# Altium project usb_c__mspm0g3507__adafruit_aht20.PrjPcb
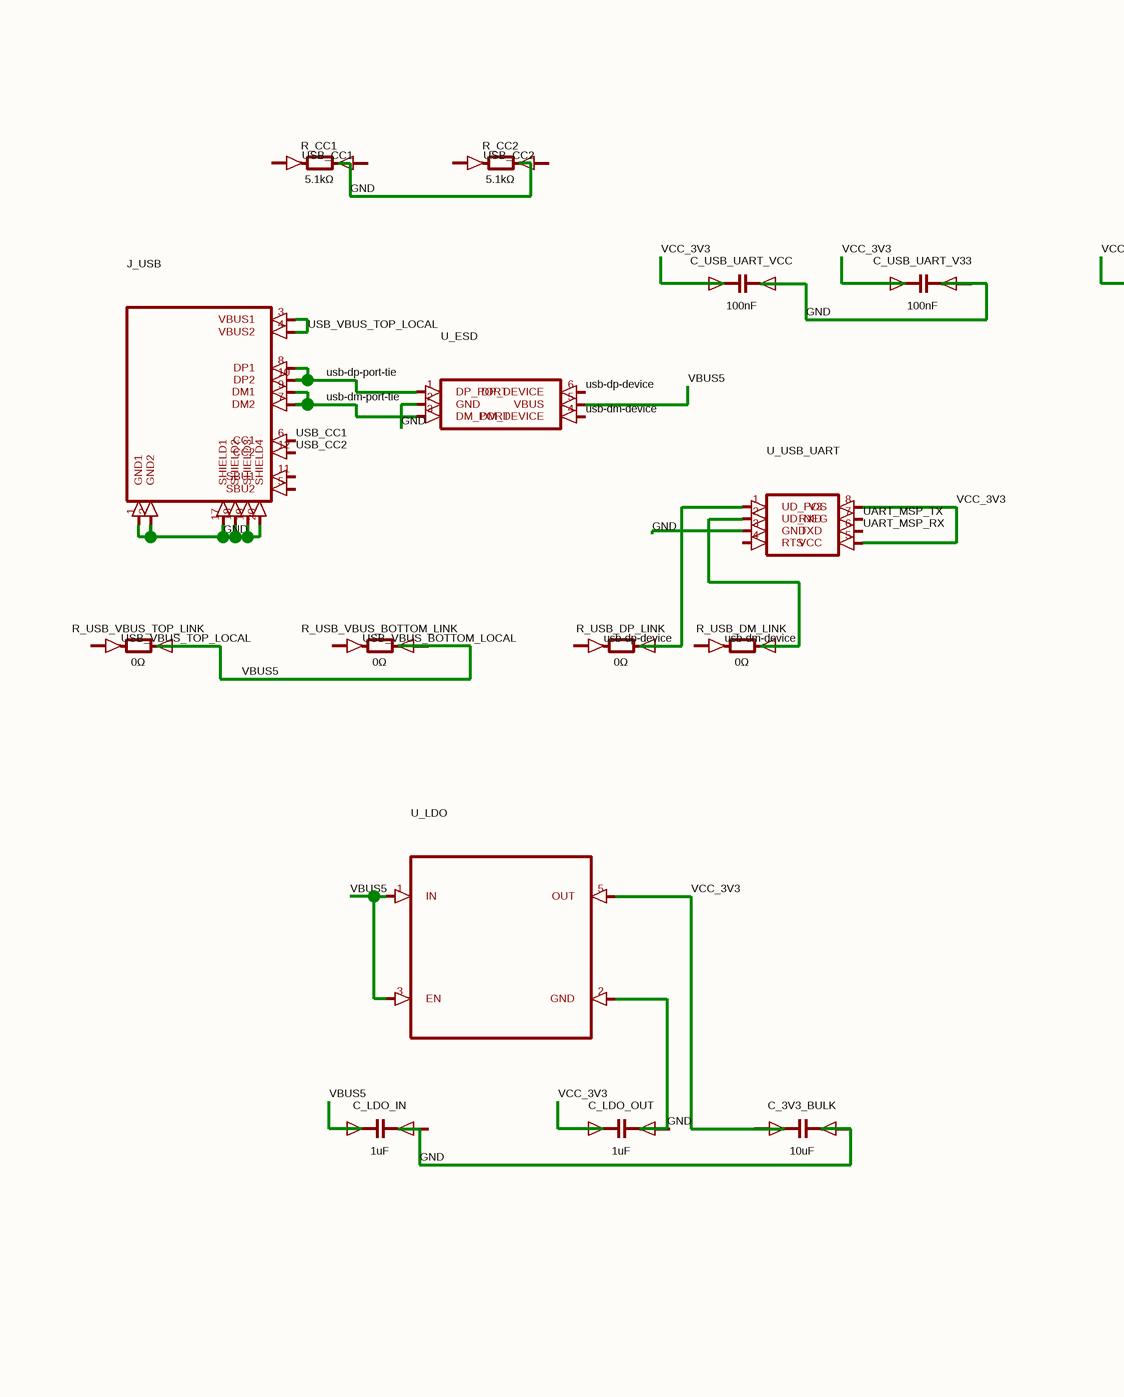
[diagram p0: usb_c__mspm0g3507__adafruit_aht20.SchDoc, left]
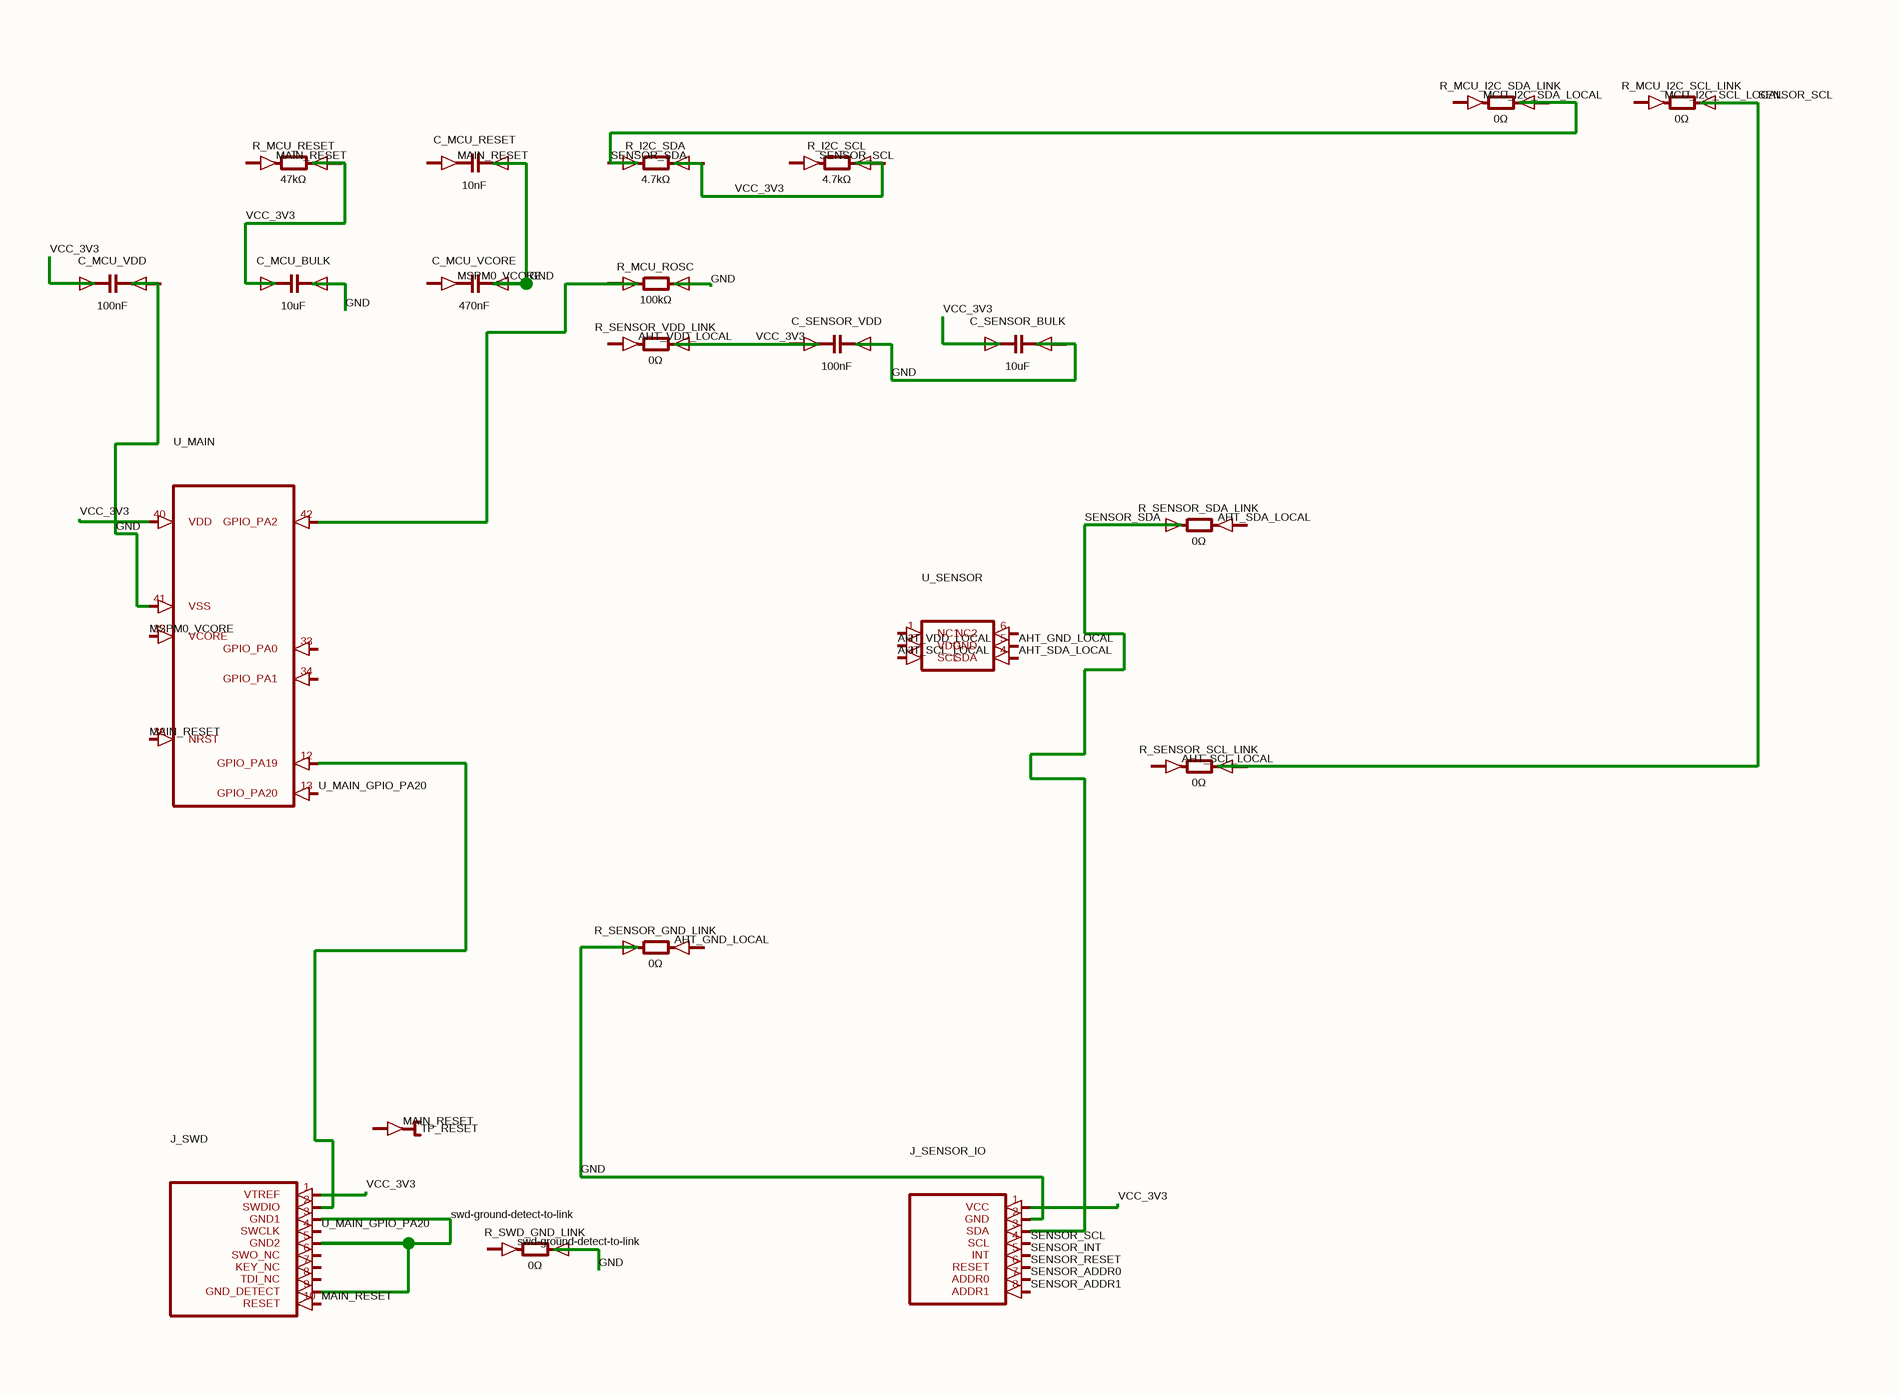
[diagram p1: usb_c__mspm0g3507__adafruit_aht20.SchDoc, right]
1 sheet, 37 parts. Net scope: global (net labels, ports and power ports of the same name join across sheets).
Board file: usb_c__mspm0g3507__adafruit_aht20.PcbDoc

## Sheet usb_c__mspm0g3507__adafruit_aht20.SchDoc
size 286 x 151 mm

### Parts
C_3V3_BULK  10uF
C_LDO_IN  1uF
C_LDO_OUT  1uF
C_MCU_BULK  10uF
C_MCU_RESET  10nF
C_MCU_VCORE  470nF
C_MCU_VDD  100nF
C_SENSOR_BULK  10uF
C_SENSOR_VDD  100nF
C_USB_UART_V33  100nF
C_USB_UART_VCC  100nF
J_SENSOR_IO  (no value)
J_SWD  (no value)
J_USB  (no value)
R_CC1  5.1kΩ
R_CC2  5.1kΩ
R_I2C_SCL  4.7kΩ
R_I2C_SDA  4.7kΩ
R_MCU_I2C_SCL_LINK  0Ω
R_MCU_I2C_SDA_LINK  0Ω
R_MCU_RESET  47kΩ
R_MCU_ROSC  100kΩ
R_SENSOR_GND_LINK  0Ω
R_SENSOR_SCL_LINK  0Ω
R_SENSOR_SDA_LINK  0Ω
R_SENSOR_VDD_LINK  0Ω
R_SWD_GND_LINK  0Ω
R_USB_DM_LINK  0Ω
R_USB_DP_LINK  0Ω
R_USB_VBUS_BOTTOM_LINK  0Ω
R_USB_VBUS_TOP_LINK  0Ω
TP_RESET  (no value)
U_ESD  (no value)
U_LDO  (no value)
U_MAIN  (no value)
U_SENSOR  (no value)
U_USB_UART  (no value)

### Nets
AHT_GND_LOCAL: U_SENSOR.5(GND)
AHT_SCL_LOCAL: U_SENSOR.3(SCL)
AHT_SDA_LOCAL: U_SENSOR.4(SDA)
AHT_VDD_LOCAL: U_SENSOR.2(VDD)
GND: C_3V3_BULK.1(pos) C_3V3_BULK.2(neg) C_LDO_OUT.1(pos) C_MCU_BULK.1(pos) C_MCU_BULK.2(neg) C_MCU_RESET.2(neg) C_MCU_VCORE.2(neg) C_MCU_VDD.1(pos) C_SENSOR_BULK.1(pos) C_SENSOR_BULK.2(neg) C_SENSOR_VDD.1(pos) C_SENSOR_VDD.2(neg) C_USB_UART_V33.1(pos) C_USB_UART_V33.2(neg) C_USB_UART_VCC.1(pos) C_USB_UART_VCC.2(neg) J_SENSOR_IO.1(VCC) J_SENSOR_IO.2(GND) J_SENSOR_IO.3(SDA) J_SWD.1(VTREF) J_USB.1(GND1) J_USB.2(GND2) J_USB.17(SHIELD1) J_USB.18(SHIELD2) J_USB.19(SHIELD3) J_USB.20(SHIELD4) R_MCU_I2C_SDA_LINK.2(cathode) R_MCU_RESET.2(cathode) R_MCU_ROSC.2(cathode) R_SENSOR_GND_LINK.1(anode) R_SENSOR_SDA_LINK.1(anode) R_SENSOR_VDD_LINK.2(cathode) R_SWD_GND_LINK.2(cathode) R_USB_DM_LINK.2(cathode) U_ESD.2(GND) U_LDO.2(GND) U_LDO.5(OUT) U_MAIN.40(VDD) U_MAIN.41(VSS) U_USB_UART.2(UD_NEG) U_USB_UART.3(GND) U_USB_UART.5(VCC) U_USB_UART.8(V3)  [also labelled SENSOR_SDA, VCC_3V3]
MAIN_RESET: J_SWD.10(RESET) U_MAIN.38(NRST)
MSPM0_VCORE: U_MAIN.32(VCORE)
SENSOR_ADDR0: J_SENSOR_IO.7(ADDR0)
SENSOR_ADDR1: J_SENSOR_IO.8(ADDR1)
SENSOR_INT: J_SENSOR_IO.5(INT)
SENSOR_RESET: J_SENSOR_IO.6(RESET)
SENSOR_SCL: J_SENSOR_IO.4(SCL) R_MCU_I2C_SCL_LINK.2(cathode) R_SENSOR_SCL_LINK.2(cathode)
swd-ground-detect-to-link: J_SWD.3(GND1) J_SWD.5(GND2) J_SWD.9(GND_DETECT)
U_MAIN_GPIO_PA20: J_SWD.4(SWCLK) U_MAIN.13(GPIO_PA20)
UART_MSP_RX: U_USB_UART.6(TXD)
UART_MSP_TX: U_USB_UART.7(RXD)
usb-dm-device: U_ESD.4(DM_DEVICE)
usb-dm-port-tie: J_USB.7(DM2) J_USB.9(DM1) U_ESD.3(DM_PORT)
usb-dp-device: U_ESD.6(DP_DEVICE)
usb-dp-port-tie: J_USB.8(DP1) J_USB.10(DP2) U_ESD.1(DP_PORT)
USB_CC1: J_USB.6(CC1)
USB_CC2: J_USB.12(CC2)
USB_VBUS_TOP_LOCAL: J_USB.3(VBUS1) J_USB.4(VBUS2)
VBUS5: C_LDO_IN.1(pos) R_USB_VBUS_BOTTOM_LINK.2(cathode) R_USB_VBUS_TOP_LINK.2(cathode) U_ESD.5(VBUS) U_LDO.1(IN) U_LDO.3(EN)
NetJ_SWD_2: J_SWD.2(SWDIO) U_MAIN.12(GPIO_PA19)
NetR_MCU_ROSC_1: R_MCU_ROSC.1(anode) U_MAIN.42(GPIO_PA2)
NetR_USB_DP_LINK_2: R_USB_DP_LINK.2(cathode) U_USB_UART.1(UD_POS)

Not connected (* = marked no-connect by the designer): C_LDO_IN 2(neg); C_LDO_OUT 2(neg); C_MCU_RESET 1(pos); C_MCU_VCORE 1(pos); C_MCU_VDD 2(neg); J_SWD 6(SWO_NC) 7(KEY_NC) 8(TDI_NC); J_USB 5(SBU2) 11(SBU1); R_CC1 1(anode) 2(cathode); R_CC2 1(anode) 2(cathode); R_I2C_SCL 1(anode) 2(cathode); R_I2C_SDA 1(anode) 2(cathode); R_MCU_I2C_SCL_LINK 1(anode); R_MCU_I2C_SDA_LINK 1(anode); R_MCU_RESET 1(anode); R_SENSOR_GND_LINK 2(cathode); R_SENSOR_SCL_LINK 1(anode); R_SENSOR_SDA_LINK 2(cathode); R_SENSOR_VDD_LINK 1(anode); R_SWD_GND_LINK 1(anode); R_USB_DM_LINK 1(anode); R_USB_DP_LINK 1(anode); R_USB_VBUS_BOTTOM_LINK 1(anode); R_USB_VBUS_TOP_LINK 1(anode); TP_RESET 1(pin1); U_MAIN 33(GPIO_PA0) 34(GPIO_PA1); U_SENSOR 1(NC1) 6(NC2); U_USB_UART 4(RTS)

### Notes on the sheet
- Labels drawn without touching a wire or pin: AHT_GND_LOCAL, AHT_SCL_LOCAL, AHT_SDA_LOCAL, AHT_VDD_LOCAL, MAIN_RESET, MCU_I2C_SCL_LOCAL, MCU_I2C_SDA_LOCAL, MSPM0_VCORE, SENSOR_SCL, swd-ground-detect-to-link, usb-dm-device, usb-dp-device, USB_CC1, USB_CC2, USB_VBUS_BOTTOM_LOCAL, USB_VBUS_TOP_LOCAL

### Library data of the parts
C_3V3_BULK C_LDO_IN C_LDO_OUT C_MCU_BULK C_MCU_RESET C_MCU_VCORE C_MCU_VDD C_SENSOR_BULK C_SENSOR_VDD C_USB_UART_V33 C_USB_UART_VCC = capacitor_right
J_SENSOR_IO = J_SENSOR_IO
J_SWD = J_SWD
J_USB = J_USB
R_CC1 R_CC2 R_I2C_SCL R_I2C_SDA R_MCU_I2C_SCL_LINK R_MCU_I2C_SDA_LINK R_MCU_RESET R_MCU_ROSC R_SENSOR_GND_LINK R_SENSOR_SCL_LINK R_SENSOR_SDA_LINK R_SENSOR_VDD_LINK R_SWD_GND_LINK R_USB_DM_LINK R_USB_DP_LINK R_USB_VBUS_BOTTOM_LINK R_USB_VBUS_TOP_LINK = boxresistor_right
TP_RESET = testpoint_right
U_ESD = U_ESD
U_LDO = U_LDO
U_MAIN = U_MAIN
U_SENSOR = U_SENSOR
U_USB_UART = U_USB_UART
